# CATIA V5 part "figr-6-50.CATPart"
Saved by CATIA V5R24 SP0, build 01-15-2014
Part number: Part1
Bounding box of the stored display mesh (mm): x -54.76 to 54.76, y -32.885 to 32.885, z 0 to 59
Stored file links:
  D:\KAVITA\CATIA V5-6R2014 Project_ Kavita\CATIA V5-6R2014_partfiles\Partfiles\c06_catia_v5-6r2014_prt\figr-6-50.CATPart
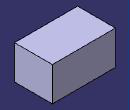
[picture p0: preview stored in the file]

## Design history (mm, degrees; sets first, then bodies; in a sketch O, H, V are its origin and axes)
Body1 (main body)
  Sketch1 on xy-plane, origin (0, 0, 0), H (1, 0, 0), V (0, 1, 0)
    line L1 (-54.7599, 32.8853) -> (54.7599, 32.8853)
    line L2 (54.7599, 32.8853) -> (54.7599, -32.8853)
    line L3 (54.7599, -32.8853) -> (-54.7599, -32.8853)
    line L4 (-54.7599, -32.8853) -> (-54.7599, 32.8853)
    axis line L5 (54.7599, -32.8853) -> (-54.7599, 32.8853)
    horizontal: L1 H, L3 H
    vertical: L2 V, L4 V
    midpoint: O L5
  Pad1: profile Sketch1, direction (0, 0, 1), length 59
